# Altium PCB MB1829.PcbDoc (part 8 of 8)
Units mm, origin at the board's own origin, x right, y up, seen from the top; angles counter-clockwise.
Board outline 90 x 110 mm, 6 copper layers (Top Layer, Signal Layer 1, Signal Layer 2, Signal Layer 3, Signal Layer 4, Bottom Layer), stack 1.578 mm thick; 466 components, 354 nets, 2058 pads, 1522 vias.
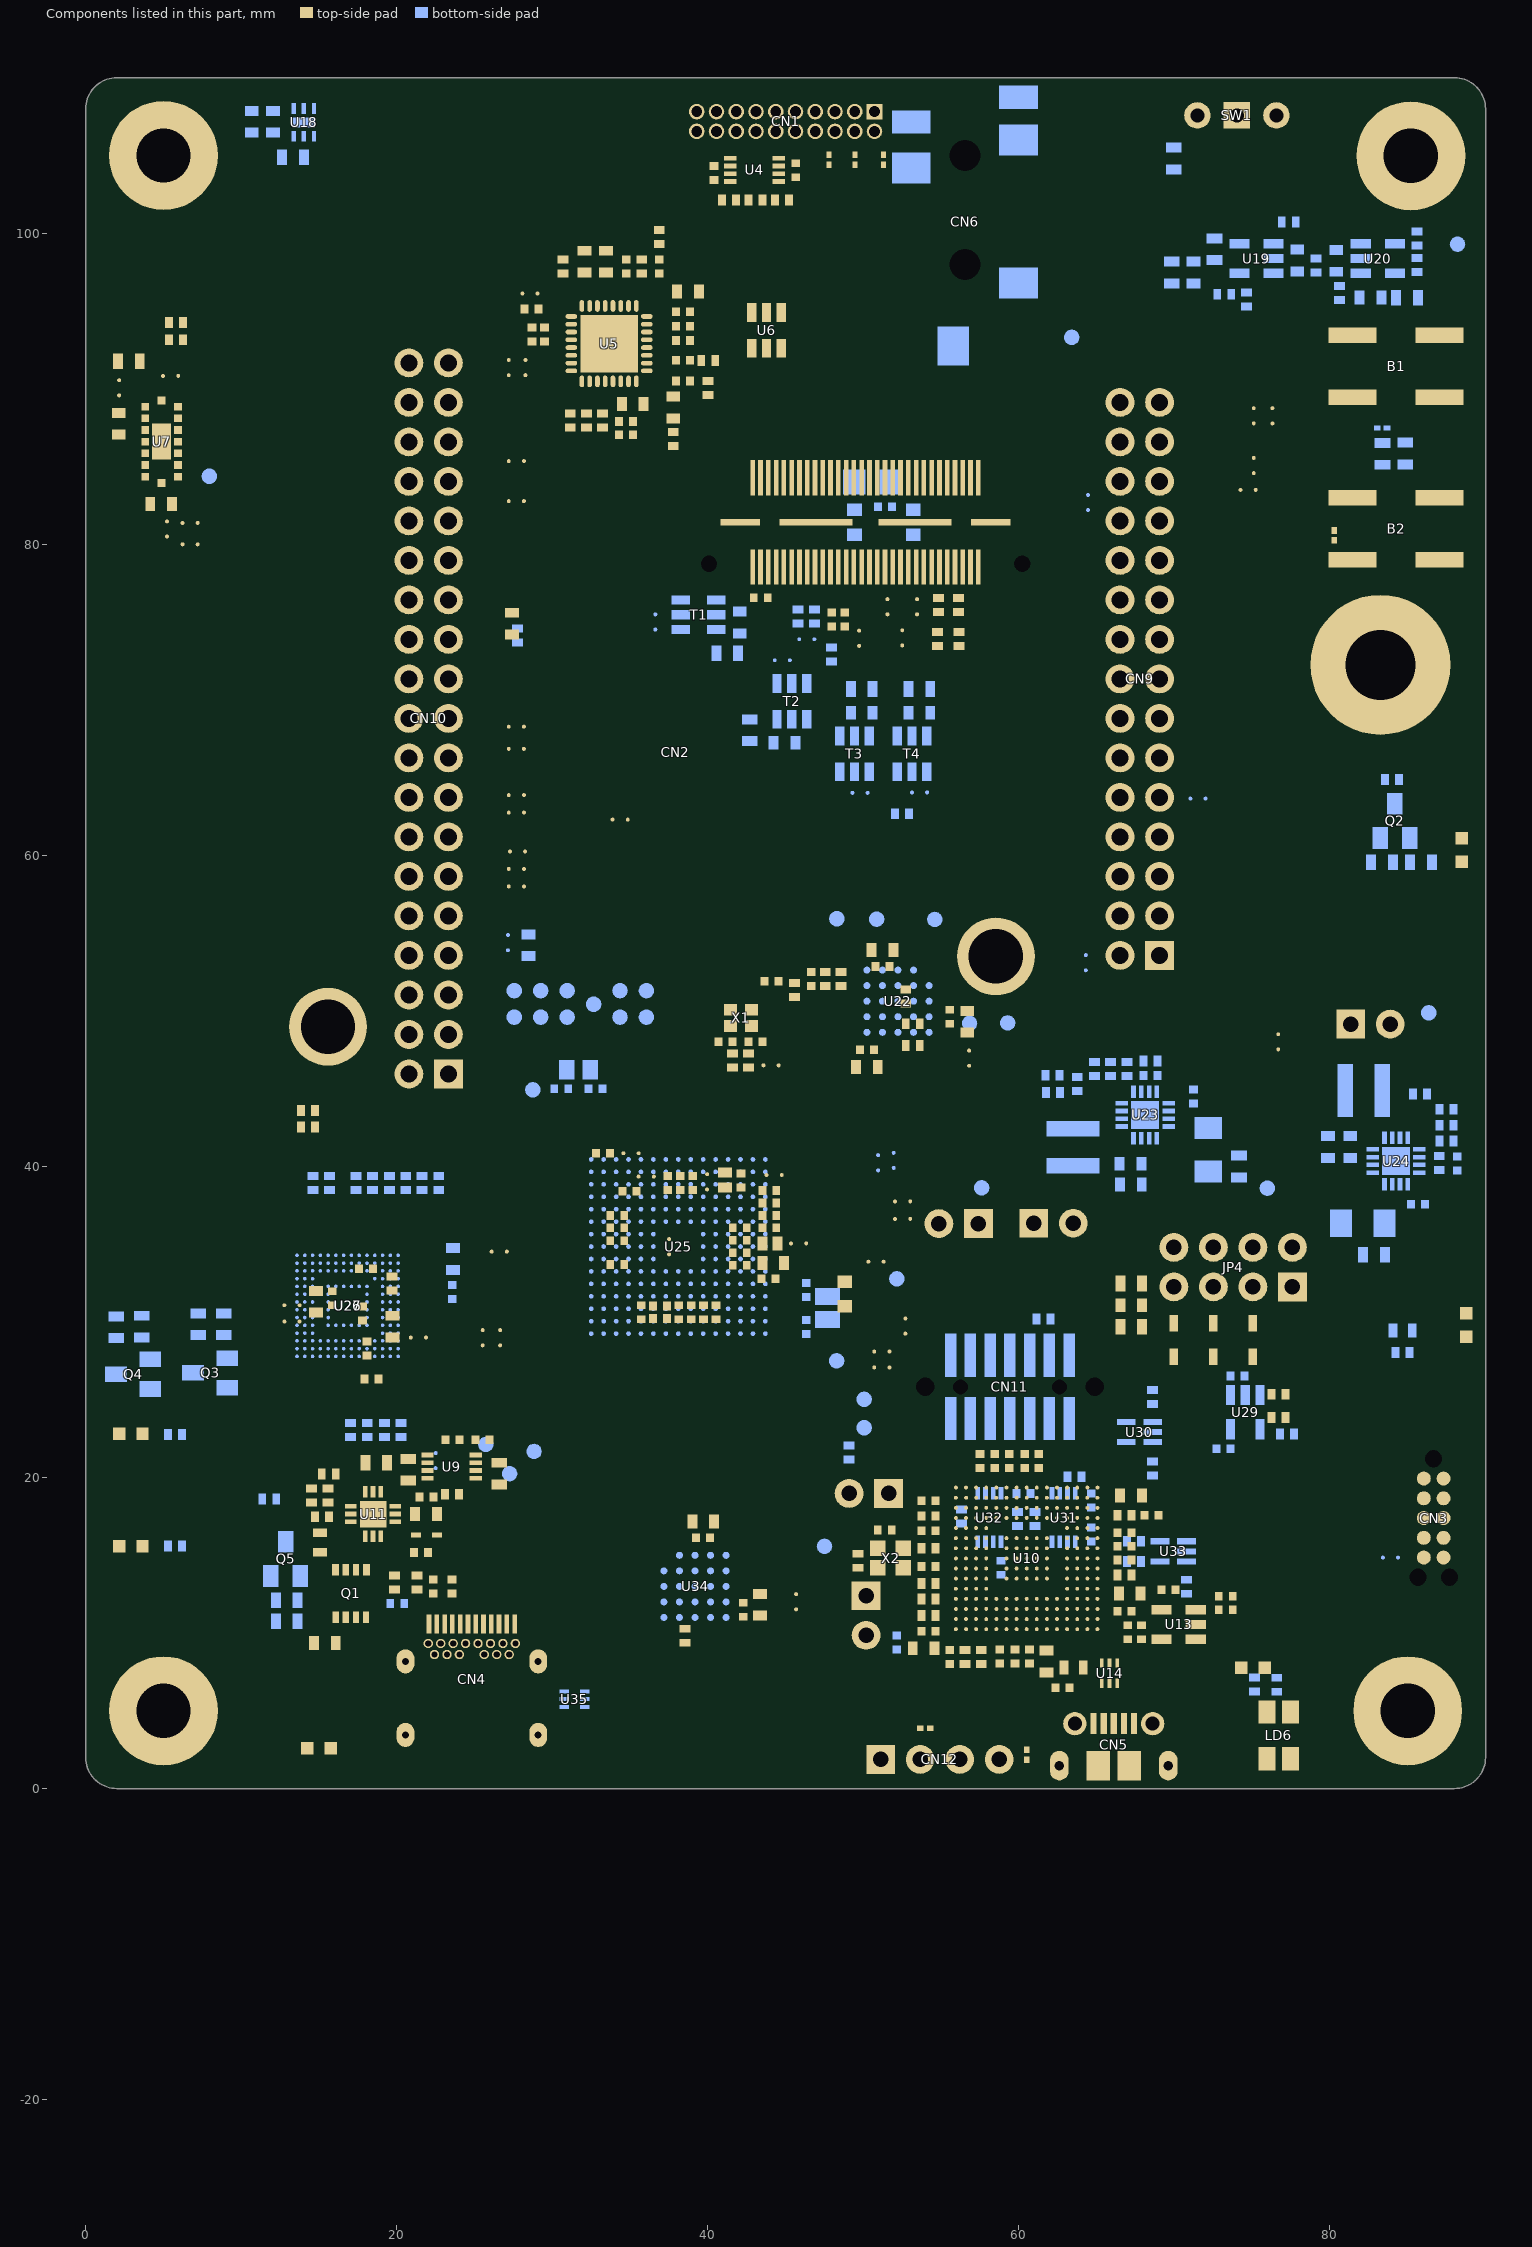
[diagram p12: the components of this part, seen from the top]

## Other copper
Top Layer:
  rectangle: 13.3,106.8 14.75,107.45
  region net GND: 88.225,34.2 88.225,36.2 87.225,36.2 87.225,34.2
  region net GND: 88.425,98.325 88.425,100.325 87.425,100.325 87.425,98.325
  region net GND: 2.425,26.8 2.425,28.8 1.425,28.8 1.425,26.8
  region net GND: 2.425,77.159 2.425,79.159 1.425,79.159 1.425,77.159
  pour cut-out: 41.45,50.675 41.725,50.95 43.4,50.95 43.65,50.7 43.65,46.018 43.2,45.568 43.2,40.654 42.726,40.18 41.749,40.18 41.245,40.684 41.245,41.66 41.7,42.115 41.7,45.25 41.475,45.475 41.009,45.475 40.725,45.759 40.725,48.199 40.575,48.349 40.575,49.925 40.725,50.075 41.15,50.075 41.45,50.375
  pour cut-out: 1.175,29.05 1.175,26.55 2.675,26.55 2.675,29.05
  pour cut-out: 1.175,79.4 1.175,76.9 2.675,76.9 2.675,79.4
  pour cut-out: 87.175,100.6 87.175,98.1 88.675,98.1 88.675,100.6
  pour cut-out: 86.975,36.45 86.975,33.95 88.475,33.95 88.475,36.45
  text "1" at 23.082,107.531 h2
  text ".Layer_Name" at 11.322,-18.839 h3
  text ".GTL" at 53.016,-18.839 h3
Signal Layer 1:
  text "2" at 24.632,107.531 h2
  text ".Layer_Name" at 11.328,-18.77 h3
  text ".G1" at 53.023,-18.77 h3
Signal Layer 2:
  pour cut-out: 25.625,11.075 25.625,8.875 25.37,8.62 24.305,8.62 23.95,8.975 23.95,11.025 24.05,11.125 25.575,11.125
  text "3" at 26.082,107.553 h2
  text ".Layer_Name" at 11.297,-18.787 h3
  text ".G2" at 52.991,-18.787 h3
Signal Layer 3:
  pour cut-out: 26.525,41.075 19.7,41.075 17.9,39.275 14.575,39.275 13.5,38.2 13.5,24.85 16.1,22.25 21.55,22.25 23.725,24.425 27.25,24.425 27.85,25.025 27.85,39.75
  pour cut-out: 36.775,13.625 37.35,13.625 39.775,11.2 39.775,9.796 39.454,9.475 38.725,9.475 38.325,9.875 38.325,10.7 36.55,12.475 36.55,13.4
  text "4" at 28.332,107.531 h2
  text ".Layer_Name" at 11.328,-18.77 h3
  text ".G3" at 53.023,-18.77 h3
Signal Layer 4:
  text "5" at 29.882,107.553 h2
  text ".Layer_Name" at 11.328,-18.77 h3
  text ".G4" at 53.023,-18.77 h3
Bottom Layer:
  pour cut-out: 66.85,42.3 66.85,40.925 66.817,40.958 61.322,40.958 61.322,41.947 61.425,42.05 61.911,41.564 65.637,41.564 66.378,42.305 66.75,42.305
  pour cut-out: 70.843,47.975 71.725,47.093 71.725,44.043 71.918,43.85 72,43.932 72,47.205 71.103,48.103
  pour cut-out: 88.3,42.302 88.649,41.953 88.825,41.953 88.825,44.146 87.296,44.146 87.124,43.975 87.124,42.726 87.557,42.293 88.3,42.293
  pour cut-out: 33.3,47.325 33.4,47.225 33.4,45.7 33.225,45.525 33.225,44.425 33.069,44.269 32.619,44.269 32.475,44.125 32.475,42.875 34.282,41.068 34.282,40.533 34.199,40.45 32.5,40.45 30.9,42.05 30.9,44 30.7,44.2 30.3,44.2 30.125,44.375 30.125,45.525 29.95,45.7 29.95,47.095 30.18,47.325
  pour cut-out: 36.875,41.55 36.875,51.994 37.927,53.046 37.927,54.476 37.309,55.095 37.309,55.875 41.486,60.051 43.209,60.051 44.199,61.041 56.022,61.041 56.235,61.254 56.235,76.399 55.783,76.851 55.783,79.993 54.35,81.426 54.35,82.058 54.35,82.75 54.362,82.738 58.031,82.738 58.043,82.75 58.043,84.398 56.231,86.21 54.81,86.21 54.412,85.813 52.887,85.813 52.887,86.726 53.652,87.49 56.761,87.49 59.173,85.078 59.173,78.102 59.625,77.65 59.625,59.85 57.471,57.696 47.371,57.696 40.225,50.55 40.225,40.375 40.122,40.272 37.339,40.272 36.75,40.861
  pour cut-out: 34.4,28.45 30.25,24.3 22.1,24.3 20.825,23.025 16.275,23.025 13.15,26.15 13.15,38.25 15.7,40.8 28.05,40.8 30.7,38.15 33.85,38.15 34.4,37.6
  pour cut-out: 31.15,23.125 31.15,10.7 32.775,9.075 45.1,9.075 46.75,10.725 46.75,23.75 41.75,28.75 41.75,30.025 39.8,31.975 36.825,31.975 35.525,30.675 35.525,27.975 34.475,26.925 34.475,26.45
  pour cut-out: 40.85,44.217 40.225,43.592 40.225,38.05 40.45,37.825 40.7,37.825 41.55,38.675 43.15,38.675 43.475,39 44.875,39 47.825,41.95 47.825,43.47 48.155,43.8 52.725,43.8 55.9,46.975 55.9,51.475 53.625,53.75 43.625,53.75 40.85,50.975
  text "6" at 31.082,107.553 h2
  text ".GBL" at 41.761,-18.675 h3
  text ".Layer_Name" at 83.075,-18.675 h3
Multi-Layer:
  pour cut-out: 6.75,101.85 17.475,101.85 17.475,109.25 6.75,109.25
  pour cut-out: 31.375,109.15 31.375,107.15 22.875,107.15 22.875,109.15

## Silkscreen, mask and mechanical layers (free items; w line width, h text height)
Top Overlay:
  drawing of 421 lines, arcs and shapes, not listed
  text "Temp" at 9.6,107.4 h1.5
  text "Pad" at 10.325,106 h1.5
  text "SW1" at 76.45,105 h1.5
  text "E" at 1.075,95.783 h10
  text "USER" at 85.425,95.525 h1.7
  text "CN10" at 19.225,93.5 h1.5
  text "PD1" at 24.8,92.4 h1.52
  text "PG8" at 16,91.2 h1.5
  text "PC4|PG14" at 71,89.6 h1.5
  text "PG7" at 16,88.7 h1.5
  text "PD0" at 24.8,88.599 h1.52
  text "PA6" at 61.7,88.599 h1.52
  text "PF5" at 16,86.3 h1.5
  text "PA5|PG13" at 71,86.3 h1.5
  text "PG0" at 24.8,86.216 h1.52
  text "CN2" at 54.8,86.099 h1.52
  text "PB1" at 61.7,86.1 h1.52
  text "RESET" at 84.625,84.9 h1.7
  text "PB10" at 61.7,83.699 h1.52
  text "PA4" at 71,83.7 h1.5
  text "PA3" at 16,83.6 h1.5
  text "PF15" at 24.8,83.499 h1.52
  text "PB11" at 61.7,81.2 h1.52
  text "PE7" at 16,81 h1.5
  text "PC5" at 71,81 h1.5
  text "PF14" at 24.8,80.6 h1.52
  text "PA0" at 71,78.5 h1.5
  text "PD15" at 16,78.4 h1.5
  text "GND" at 24.8,78.399 h1.52
  text "PB0" at 61.7,78.399 h1.52
  text "MB1829B" at 3,76.75 h2.5
  text "AGND" at 24.799,76.299 h1.52
  text "GND" at 61.7,75.999 h1.52
  text "PB2" at 71,75.9 h1.5
  text "PE11" at 16,75.8 h1.5
  text "PF12" at 16,73.3 h1.5
  text "VDDA" at 24.799,72.5 h1.52
  text "J" at 2,71.5 h12
  text "PF1" at 61.7,71 h1.52
  text "1V8" at 71,70.9 h1.5
  text "PD3" at 24.925,68.999 h1.52
  text "GND" at 71,68.5 h1.5
  text "PF0" at 61.7,68.399 h1.52
  text "PF13" at 16.2,68 h1.5
  text "GND" at 71,65.9 h1.5
  text "PA7" at 16.2,65.7 h1.5
  text "PD7" at 61.7,65.7 h1.52
  text "PB12" at 24.925,65.2 h1.52
  text "PD6" at 61.7,63.399 h1.52
  text "5V" at 71,63.3 h1.5
  text "PD10|PB13" at 29.2,63.282 h1.5
  text "PG15" at 16.2,63 h1.5
  text "/ 3V3" at 89.399,62.375 h1.7 r90
  text "VDD" at 87.8,62.05 h1.7 r90
  text "PD4|PD11" at 24.925,61.016 h1.5
  text "PB4" at 61.7,60.9 h1.52
  text "3V3" at 71,60.7 h1.5
  text "PG11" at 16.2,60.6 h1.5
  text "PB3" at 61.7,58.299 h1.52
  text "PD9" at 29.2,58.199 h1.52
  text "NRST" at 71,58.2 h1.5
  text "PG10" at 16.2,58 h1.5
  text "PB15" at 61.7,55.799 h1.52
  text "IOREF" at 71,55.7 h1.5
  text "PG9" at 16.2,55.6 h1.5
  text "PD12" at 25.125,55.508 h1.52
  text "GND" at 16.2,53.3 h1.3
  text "PE4" at 25.15,53.2 h1.52
  text "PB14" at 61.7,53.2 h1.52
  text "5V_VIN" at 71,53.2 h1.5
  text "VREFP" at 15.9,52 h1.2
  text "3V3" at 82.675,51.175 h1.7
  text "PE5" at 25.125,50.591 h1.52
  text "PE6" at 25.151,47.936 h1.52
  text "JP1" at 81.725,46.55 h1.5
  text "PE2" at 25.125,45.55 h1.52
  text "PG13" at 16,45 h1.5
  text "PG14" at 16,43.8 h1.5
  text "JP3" at 56.25,38.325 h1.5
  text "JP2" at 60.325,38.325 h1.5
  text "JP4" at 68.4,33.725 h1.5 r90
  text "VDD_MCU" at 52.8,33.575 h1.5
  text "VDD" at 62.025,33.575 h1.5
  text "5V" at 87.9,27.025 h1.7
  text "CN11" at 66.95,24.425 h1.5 r90
  text "TAG" at 86.425,24.15 h1.7
  text "USER" at 0.825,20.825 h1.7
  text "JP5" at 49,20.575 h1.5
  text "GREEN" at 0.65,19.45 h1.7
  text "USER" at 0.725,13.325 h1.7
  text "RED" at 1.425,11.8 h1.7
  text "JP6" at 48.575,10.375 h1.5 r90
  text "OVC" at 73.575,8.55 h1.5
  text "USB" at 70.2,6.475 h1.7
  text "USB" at 15.525,5.65 h1.7
  text "STLK" at 69.6,5.175 h1.7
  text "Type-C" at 14.675,4.325 h1.7
  text "3V3 / STLK" at 52.091,3.425 h1.7 r90
  text "COM" at 71.269,2.573 h1.7
  text "USBC 5V" at 9.8,0.725 h1.7
  text "CN12" at 49.35,0.425 h1.5 r90
  text ".Layer_Name" at 11.322,-18.839 h3
  text ".GTO" at 53.016,-18.839 h3
Bottom Overlay:
  lines w0.1: 20.454,0.38 20.454,1.005 ; 20.454,1.305 20.454,1.93 ; 20.454,2.255 20.454,2.4 ; 20.454,4.45 20.454,4.82 ; 20.454,5.145 20.454,5.77 ; 20.454,6.195 20.454,6.82 ; 20.454,9.275 20.454,9.52 ; 20.454,9.755 20.454,10.38 ; 20.454,10.375 20.749,10.375 ; 21.074,10.375 21.699,10.375 ; 22.089,10.375 22.714,10.375 ; 23.014,10.375 23.639,10.375 ; 23.964,10.375 24.589,10.375 ; 25.014,10.375 25.639,10.375 ; 25.939,10.375 26.564,10.375 ; 26.889,10.375 27.514,10.375 ; 27.789,10.375 28.339,10.375 ; 28.574,10.375 29.199,10.375 ; 29.194,0.38 29.194,1.005 ; 29.194,1.305 29.194,1.93 ; 29.194,2.255 29.194,2.4 ; 29.194,4.45 29.194,4.82 ; 29.194,5.145 29.194,5.77 ; 29.194,6.195 29.194,6.82 ; 29.194,9.275 29.194,9.52 ; 29.194,9.755 29.194,10.38 ; 62.1,2.525 62.1,2.94 ; 62.1,3.215 62.1,3.765 ; 62.1,4 62.1,4.625 62.6,4.625 ; 62.99,4.625 63.615,4.625 ; 63.915,4.625 64.54,4.625 ; 64.865,4.625 65.49,4.625 ; 65.32,52.039 66.195,52.039 ; 65.915,4.625 66.54,4.625 ; 66.84,4.625 67.465,4.625 ; 67.79,4.625 68.415,4.625 ; 68.69,4.625 69.24,4.625 ; 69.37,52.039 70.245,52.039 70.246,52.243 ; 69.475,4.625 70.1,4.625 70.1,4 ; 70.1,2.525 70.1,2.94 ; 70.1,3.215 70.1,3.765 ; 21.475,0.688 21.475,3.738 26.675,3.738 26.675,0.688 21.475,0.688 ; 62.19,105.7 62.19,108.775 67.415,108.775 67.415,105.7 62.19,105.7 ; 63.975,5.126 63.975,8.175 68.2,8.175 68.2,5.126 63.975,5.126
  lines w0.12: 17.775,45.875 17.775,46.2 19.225,47.65 ; 17.825,51.75 18.664,51.75 19.35,51.064 ; 24.745,50.133 25.795,49.083 25.795,48.9 ; 38.42,105.685 38.92,105.685 ; 38.42,105.894 38.42,106.894 ; 38.42,107.685 38.42,108.685 38.92,108.685 ; 39.275,80.95 39.275,81.725 ; 39.275,82.225 39.275,82.95 ; 39.275,83.5 39.275,84.275 ; 39.275,84.775 39.275,85.5 ; 39.283,79.7 39.283,80.425 ; 39.9,85.5 40.625,85.5 ; 39.92,105.685 40.92,105.685 ; 39.92,108.685 40.92,108.685 ; 41.2,85.5 41.975,85.5 ; 41.92,105.685 42.92,105.685 ; 41.92,108.685 42.92,108.685 ; 42.475,85.5 43.2,85.5 ; 43.1,77.375 43.825,77.375 ; 43.775,85.5 44.55,85.5 ; 43.92,105.685 44.92,105.685 ; 43.92,108.685 44.92,108.685 ; 44.325,77.375 45.1,77.375 ; 45.05,85.5 45.775,85.5 ; 45.92,105.685 46.92,105.685 ; 45.92,108.685 46.92,108.685 ; 46.4,85.5 47.175,85.5 ; 47.675,85.5 48.4,85.5 ; 47.92,105.685 48.92,105.685 ; 47.92,108.685 48.92,108.685 ; 49.75,77.375 50.475,77.375 ; 49.92,105.685 50.92,105.685 ; 49.92,108.685 50.92,108.685 ; 51.175,77.366 51.95,77.366 ; 51.58,105.894 51.58,106.894 ; 51.58,107.685 51.58,108.685 ; 52.45,77.366 53.175,77.366 ; 53,85.475 53.775,85.475 ; 53.783,77.382 54.558,77.382 ; 54.275,85.475 55,85.475 55.775,85.475 ; 55.058,77.382 55.783,77.382 ; 56.275,85.475 57,85.475 57.775,85.475 ; 56.375,77.375 57.15,77.375 ; 57.65,77.375 58.375,77.375 ; 58.275,85.475 59,85.475 59.775,85.475 ; 59,77.375 59.775,77.375 ; 60.275,77.375 61,77.375 61,78.025 ; 60.275,85.475 61,85.475 61,84.75 ; 61,79.425 61,80.15 ; 61,80.65 61,81.425 ; 61,81.95 61,82.675 ; 61,83.175 61,83.95 ; 75.35,26.5 76.5,26.5 76.95,26.05 ; 86.325,100.375 86.325,98.825 86.325,97.2 86.325,96.75 86.5,96.575 87.4,96.575
  text "AUDIO" at 67.15,107.35 h1.7
  text "CN1" at 38,107 h1.3
  text "JACK" at 66.85,105.975 h1.7
  text "0" at 71.975,105.8 h1.5 r90
  text "1" at 76.2,105.3 h1.5 r270
  text "CN6" at 64.9,104.35 h1.5
  text "G" at 25.175,101.65 h8
  text "BOOT0" at 73.575,101.375 h1.5 r270
  text "F" at 32.8,101.3 h10
  text "S" at 47.525,97.6 h10
  text "2V8" at 89.325,97.3 h1.7
  text "C" at 34,92.5 h10
  text "CN9" at 69,91.4 h1.5
  text "1V8" at 64.516,91.141 h1.7
  text "PG8" at 19,91 h1.5
  text "PD1" at 27.258,91 h1.5
  text "PC4|PG14" at 77.313,88.987 h1.52
  text "PA6" at 64.7,88.7 h1.5
  text "PD0" at 27.441,88.616 h1.5
  text "PG7" at 19,88.5 h1.5
  text "I" at 41,88.5 h13.5
  text "H" at 52.5,88 h16
  text "PA5|PG13" at 77.242,86.287 h1.52
  text "PB1" at 64.7,86.2 h1.5
  text "PG0" at 27.515,86.016 h1.5
  text "PF5" at 19,85.999 h1.52
  text "PB10" at 64.7,83.9 h1.5
  text "CN2" at 43.1,83.825 h1.7
  text "PF15" at 28.047,83.516 h1.5
  text "PA4" at 73.403,83.5 h1.52
  text "PA3" at 19,83.399 h1.52
  text "PF14" at 28.035,81 h1.5
  text "PC5" at 73.49,81.016 h1.52
  text "PE7" at 19,80.8 h1.52
  text "PB11" at 64.7,80.6 h1.5
  text "GND" at 27.838,78.516 h1.5
  text "PA0" at 73.404,78.516 h1.52
  text "PB0" at 64.7,78.5 h1.5
  text "PD15" at 19,78.299 h1.52
  text "AGND" at 28.301,76.014 h1.3
  text "GND" at 64.7,76 h1.5
  text "PB2" at 73.397,75.9 h1.52
  text "PE11" at 19,75.8 h1.52
  text "PF12" at 19,73.3 h1.52
  text "VDDA" at 28.723,72.3 h1.5
  text "PF1" at 64.7,70.9 h1.5
  text "1V8" at 73.215,70.816 h1.52
  text "PF0" at 64.7,68.5 h1.5
  text "PF13" at 19,68.299 h1.52
  text "PD3" at 27.444,68.316 h1.5
  text "GND" at 73.882,68.316 h1.52
  text "GND" at 73.882,65.816 h1.52
  text "PB12" at 28.106,65.8 h1.5
  text "PD7" at 64.7,65.8 h1.5
  text "PA7" at 19,65.5 h1.52
  text "PB13|PD10" at 31.815,63.482 h1.5
  text "PD6" at 64.7,63.3 h1.5
  text "5V" at 74.297,63.216 h1.52
  text "PG15" at 19,63 h1.5
  text "PD4|PD11" at 30.96,60.882 h1.5
  text "3V3" at 73.303,60.816 h1.52
  text "PB4" at 64.7,60.8 h1.5
  text "PG11" at 19,60.5 h1.5
  text "PB3" at 64.7,58.3 h1.5
  text "PD9" at 27.446,58.216 h1.5
  text "NRST" at 74.575,58.116 h1.52
  text "PG10" at 19,58 h1.5
  text "PB15" at 64.7,55.8 h1.5
  text "PD12" at 28.18,55.7 h1.5
  text "IOREF" at 74.973,55.616 h1.52
  text "PG9" at 19,55.5 h1.5
  text "PB14" at 64.7,54.2 h1.5
  text "GND" at 19,53.2 h1.5
  text "5V_VIN" at 75.524,53.171 h1.52
  text "PE4" at 27.366,52.3 h1.5
  text "VREFP" at 19,52 h1.5
  text "IDD / 3V3" at 82,51.3 h1.7 r270
  text "2" at 66.025,51.125 h1.5 r270
  text "PJ3" at 37.25,50.55 h1.5 r270
  text "PJ6" at 38.7,50.55 h1.5 r270
  text "PJ5" at 40.3,50.55 h1.5 r270
  text "PJ1" at 42.925,50.55 h1.5 r270
  text "PJ9" at 44.25,50.55 h1.5 r270
  text "PJ8" at 41.625,49.325 h1.5 r270
  text "3V3" at 87.65,48.55 h1.7 r270
  text "PJ4" at 38.7,48.025 h1.5 r270
  text "PJ7" at 40.3,48.025 h1.5 r270
  text "PJ2" at 37.275,47.975 h1.5 r270
  text "PE5" at 27.377,47.716 h1.5
  text "PJ11" at 44.275,47.45 h1.5 r270
  text "PJ10" at 42.925,47.275 h1.5 r270
  text "OP1" at 58.184,47.234 h1.5
  text "OP2" at 61.186,47.236 h1.5
  text "PE6" at 27.369,46.516 h1.5
  text "PE2" at 27.36,45.3 h1.5
  text "PG13" at 19,44.7 h1.5
  text "PG14" at 19,43.5 h1.5
  text "2" at 20.3,43.5 h1.5 r270
  text "VDD" at 59.275,40.8 h1.7
  text "PG12" at 28.225,40.725 h1.5 r270
  text "MCU" at 59.05,39.575 h1.7
  text "5V" at 78.6,38.1 h1.7
  text "PE15" at 53.575,33.725 h1.5
  text "IDD" at 62.975,33.525 h1.7
  text "IDD / MCU" at 57.9,32.025 h1.7
  text "E5V" at 74.5,27.9 h1.7 r270
  text "STLK" at 77.075,27.15 h1.7 r270
  text "PD13" at 47.275,27 h1.5
  text "USBC" at 71.975,26.6 h1.7 r270
  text "CHGR" at 69.475,26.3 h1.7 r270
  text "PG2" at 48.775,24.65 h1.5
  text "DEBUG" at 51.25,23.275 h1.7 r270
  text "PG4" at 48.825,22.875 h1.5
  text "PG6" at 25.275,18.525 h1.5 r270
  text "PG5" at 28.35,18.1 h1.5 r270
  text "PG3" at 26.75,16.8 h1.5 r270
  text "TNRST" at 52.95,16.15 h1.7
  text "PD14" at 45.55,13.963 h1.5 r270
  text "CN3" at 88.075,11.25 h1.5
  text "STLK_NRST" at 47.4,7.625 h1.4 r270
  text "USB" at 67.5,6.85 h1.7
  text "STLK" at 67.941,5.441 h1.7
  text "SWCLK" at 53.225,4.05 h1.7 r270
  text "GND" at 55.8,3.925 h1.7 r270
  text "SWIO" at 58.125,3.875 h1.7 r270
  text "3V3 / STLK" at 51.9,3.65 h1.7
  text "USB" at 25.6,2.45 h1.7
  text "CN5" at 67.1,2.275 h1.5
  text "K" at 42.04,1.97 h12
  text "Type-C" at 26.525,1.275 h1.7
  text "CN4" at 32.05,0.8 h1.5
  text ".GBO" at 41.788,-18.819 h3
  text ".Layer_Name" at 83.102,-18.819 h3
Top Paste:
  text ".Layer_Name" at 11.322,-18.839 h3
  text ".GTP" at 53.016,-18.839 h3
Bottom Paste:
  text ".GBP" at 41.761,-18.675 h3
  text ".Layer_Name" at 83.075,-18.675 h3
Top Solder:
  region: 31.375,109.15 22.875,109.15 22.875,107.15 31.375,107.15
  text ".Layer_Name" at 11.322,-18.839 h3
  text ".GTS" at 53.016,-18.839 h3
Bottom Solder:
  region: 31.375,109.15 22.875,109.15 22.875,107.15 31.375,107.15
  text ".GBS" at 41.761,-18.675 h3
  text ".Layer_Name" at 83.075,-18.675 h3
M1-Board Shape:
  lines w0.1: 0,2 ccw(c2,2) 2,0 88,0 ccw(c88,2) 90,2 90,108 ccw(c88,108) 88,110 2,110 ccw(c2,108) 0,108 0,2
  lines w0.12: 15.625,102.35 15.65,102.35 cw(c15.65,102.1) 15.9,102.1 cw(c15.65,102.1) 15.65,101.85 9.15,101.85 cw(c9.15,102.1) 8.9,102.1 ; 15.637,102.35 9.15,102.35 ccw(c9.15,102.1) 8.9,102.1 ; 17.475,102.975 cw(c17.25,102.975) 17.25,102.75 cw(c17.25,103.025) 16.975,103.025 16.975,107.575 cw(c17.225,107.575) 17.225,107.825 cw(c17.225,107.575) 17.475,107.575 17.475,103.025 ; 8.9,102.1 8.9,102.1
M2-Board Dimensions:
  text ".Layer_Name" at 11.322,-18.839 h3
  text ".GM2" at 53.016,-18.839 h3
M3-Top Dimensions:
  circle w0.1: c83.241,72.252 r2.25
  circle w0.1: c85,5 r1.75
  circle w0.1: c5,5 r1.75
  circle w0.1: c5,105 r1.75
  circle w0.1: c85.2,104.975 r1.75
M7-Top Info:
  lines w0.12: 16.64,10.05 14.904,10.05 9.998,5.144 cw(c5,5) 4.944,10 10.123,15.178 10.123,16.565 cw(c45,45) 79.877,16.565 79.877,15.178 85.056,10 cw(c85,5) 80.002,5.144 75.096,10.05 73.36,10.05 ; 16.646,10.057 ccw(c45,45) 27.6,3.5 62.4,3.5 ; 62.41,3.504 ccw(c45,45) 73.354,10.057
  text "MB1835B" at 33.697,45.038 h7
M8-Bottom Info:
  lines w0.1: 18.546,63.232 cw(c34.306,68.479) 26.306,83.035 26.306,87.479 62.306,87.479 62.306,49.479 37.056,49.479 37.056,51.979 ; 21.563,57.825 ccw(c34.306,68.479) 26.306,53.922 26.306,49.479 31.556,49.479 31.556,51.979 ; 24.579,85.479 39.579,85.479 ; 24.582,85.473 ccw(c32.96,66.217) 15.079,77.229 15.079,66.479 12.079,66.479 12.079,45.479 61.579,45.479 61.579,88.479 39.579,88.479 ; 153.106,158.027 156.106,158.027
  lines w0.12: 18.546,63.232 19.99,64.159 23.007,58.751 21.563,57.825 ; 31.556,51.979 37.056,51.979 ; 35.667,62.082 35.667,89.052 88.497,89.052 88.497,62.082 35.667,62.082
  text "MB1232A" at 47.35,74.487 h7
  text "MB1314C" at 30.426,66.851 h7
  text "MB1650C" at 24.679,63.329 h7
M14-Top Assembly:
  text ".Layer_Name" at 11.322,-18.839 h3
  text ".GM14" at 53.016,-18.839 h3
M15-Bottom Assembly:
  text ".GM15" at 41.761,-18.675 h3
  text ".Layer_Name" at 83.075,-18.675 h3
Drill Drawing:
  drawing of 558 lines, arcs and shapes, not listed
  text "THE COMPONENTS WITH PLATED THROUGH HOLE (PTH) MAY BE WELDED (CABLED) IN \"PIN-IN-PASTE\" MODE (IF NECESSARY)" at 3.298,155.754 h1.52
  text "PCB SPECIFICATIONS :" at 3.873,151.004 h3
  text "PCB : TYPE 3" at 152.285,150.771 h3
  text "A.   MATERIAL :" at 3.873,147.004 h3
  text "FR-4" at 42.373,147.004 h3
  text "TG-170" at 58.873,147.004 h3
  text "X  TG-150" at 77.123,147.004 h3
  text "TG-140" at 93.123,147.004 h3
  text "ASPECT-RATIO, AXE Z :" at 152.285,145.271 h3
  text "B.   MATERIAL FAMILY :" at 3.873,144.004 h3
  text "N/A" at 42.373,144.004 h3
  text "C.   SOLDERMASK COLOR :" at 3.873,141.004 h3
  text "GREEN" at 42.373,141.004 h3
  text "WHITE" at 58.873,141.004 h3
  text "RED" at 77.123,141.004 h3
  text "X  Blue ink PANTONE 2955" at 93.123,141.004 h3
  text "6:1 to 8:1 / LEVEL \"B\"" at 152.573,139.804 h3
  text "D.   SILKSCREEN COLOR :" at 3.873,138.004 h3
  text "X  WHITE" at 42.373,138.004 h3
  text "YELLOW" at 58.873,138.004 h3
  text "BLACK" at 77.123,138.004 h3
  text "Blue ink PANTONE 2955" at 93.123,138.004 h3
  text "E.   SURFACE FINISH :" at 3.873,135.004 h3
  text "X  ENIG" at 42.373,135.004 h3
  text "IMMERSION SILVER" at 58.873,135.004 h3
  text "IMMERSION TIN" at 93.123,135.004 h3
  text "MINIMUM PARAMETERS" at 152.331,132.923 h3
  text "HASL" at 42.373,132.004 h3
  text "HASL (PB-FREE)" at 58.873,132.004 h3
  text "GOLDEN FINGER" at 93.123,132.004 h3
  text "F.   IMPEDANCE CONTROL :" at 3.873,129.004 h3
  text "NO" at 42.373,129.004 h3
  text "X  YES  (SEE IMPEDANCE TABLE FOR DETAIL INFORMATION)" at 58.873,129.004 h3
  text "DEFAULT" at 152.331,127.423 h3
  text "G.   THROUGH VIA :" at 3.873,126.004 h3
  text "PLUG THE VIAS WHICH ARE COVERED WITH SOLDERMASK ONE OR TWO SIDE." at 42.373,126.004 h3
  text "PLUG MATERIAL :" at 42.373,123.004 h3
  text "X  SOLDERMASK" at 67.873,123.004 h3
  text "NON-CONDUCTIVE EPOXY." at 93.123,123.004 h3
  text "TRACKS : 0.08mm           / GAPS : 0.085mm" at 152.273,121.904 h3
  text "H.   STACK-UP :" at 3.873,120.004 h3
  text "SEE LAYER STACK-UP SEQUENCE FOR OVERALL THICKNESS." at 42.373,120.004 h3
  text "Symbol" at 133.228,108.097 h2.4
  text "Count" at 142.626,108.097 h2.4
  text "Hole Size" at 153.239,108.097 h2.4
  text "Plated" at 172.529,108.097 h2.4
  text "Hole Type" at 180.778,108.097 h2.4
  text "Drill Layer Pair" at 192.785,108.097 h2.4
  text "Via/Pad" at 219.548,108.097 h2.4
  text "Pad Shape" at 229.387,108.097 h2.4
  text "14" at 142.626,103.955 h2
  text "0,400mm (15,75mil)" at 153.239,103.955 h2
  text "PTH" at 172.529,103.955 h2
  text "Round" at 180.778,103.955 h2
  text "Top Layer - Bottom Layer" at 192.785,103.955 h2
  text "Pad" at 219.548,103.955 h2
  text "Rounded" at 229.387,103.955 h2
  text "4" at 142.626,99.813 h2
  text "0,450mm (17,72mil)" at 153.239,99.813 h2
  text "PTH" at 172.529,99.813 h2
  text "Slot" at 180.778,99.813 h2
  text "Top Layer - Bottom Layer" at 192.785,99.813 h2
  text "Pad" at 219.548,99.813 h2
  text "Rounded" at 229.387,99.813 h2
  text "2" at 142.626,95.671 h2
  text "0,600mm (23,62mil)" at 153.239,95.671 h2
  text "PTH" at 172.529,95.671 h2
  text "Slot" at 180.778,95.671 h2
  text "Top Layer - Bottom Layer" at 192.785,95.671 h2
  text "Pad" at 219.548,95.671 h2
  text "Rounded" at 229.387,95.671 h2
  text "20" at 142.626,91.529 h2
  text "0,700mm (27,56mil)" at 153.239,91.529 h2
  text "PTH" at 172.529,91.529 h2
  text "Round" at 180.778,91.529 h2
  text "Top Layer - Bottom Layer" at 192.785,91.529 h2
  text "Pad" at 219.548,91.529 h2
  text "Rounded" at 229.387,91.529 h2
  text "H" at 132.44,91.275 h1.84
  text "5" at 142.626,87.387 h2
  text "0,900mm (35,43mil)" at 153.239,87.387 h2
  text "PTH" at 172.529,87.387 h2
  text "Round" at 180.778,87.387 h2
  text "Top Layer - Bottom Layer" at 192.785,87.387 h2
  text "Pad" at 219.548,87.387 h2
  text "(Mixed)" at 229.387,87.387 h2
  text "2" at 142.626,83.245 h2
  text "0,970mm (38,19mil)" at 153.239,83.245 h2
  text "NPTH" at 172.529,83.245 h2
  text "Round" at 180.778,83.245 h2
  text "Top Layer - Bottom Layer" at 192.785,83.245 h2
  text "Pad" at 219.548,83.245 h2
  text "Rounded" at 229.387,83.245 h2
  text "22" at 142.626,79.103 h2
  text "1,000mm (39,37mil)" at 153.239,79.103 h2
  text "PTH" at 172.529,79.103 h2
  text "Round" at 180.778,79.103 h2
  text "Top Layer - Bottom Layer" at 192.785,79.103 h2
  text "Pad" at 219.548,79.103 h2
  text "Rounded" at 229.387,79.103 h2
  text "2" at 142.626,74.962 h2
  text "1,050mm (41,34mil)" at 153.239,74.962 h2
  text "NPTH" at 172.529,74.962 h2
  text "Round" at 180.778,74.962 h2
  text "Top Layer - Bottom Layer" at 192.785,74.962 h2
  text "Pad" at 219.548,74.962 h2
  text "Rounded" at 229.387,74.962 h2
  text "3" at 142.626,70.82 h2
  text "1,100mm (43,31mil)" at 153.239,70.82 h2
  text "NPTH" at 172.529,70.82 h2
  text "Round" at 180.778,70.82 h2
  text "Top Layer - Bottom Layer" at 192.785,70.82 h2
  text "Pad" at 219.548,70.82 h2
  text "Rounded" at 229.387,70.82 h2
  text "68" at 142.626,66.678 h2
  text "1,100mm (43,31mil)" at 153.239,66.678 h2
  text "PTH" at 172.529,66.678 h2
  text "Round" at 180.778,66.678 h2
  text "Top Layer - Bottom Layer" at 192.785,66.678 h2
  text "Pad" at 219.548,66.678 h2
  text "Rounded" at 229.387,66.678 h2
  text "2" at 142.626,62.536 h2
  text "1,190mm (46,85mil)" at 153.239,62.536 h2
  text "NPTH" at 172.529,62.536 h2
  text "Round" at 180.778,62.536 h2
  text "Top Layer - Bottom Layer" at 192.785,62.536 h2
  text "Pad" at 219.548,62.536 h2
  text "Rounded" at 229.387,62.536 h2
  text "2" at 142.626,58.394 h2
  text "2,000mm (78,74mil)" at 153.239,58.394 h2
  text "NPTH" at 172.529,58.394 h2
  text "Round" at 180.778,58.394 h2
  text "Top Layer - Bottom Layer" at 192.785,58.394 h2
  text "Pad" at 219.548,58.394 h2
  text "Rounded" at 229.387,58.394 h2
  text "2" at 142.626,54.252 h2
  text "3,200mm (125,98mil)" at 153.239,54.252 h2
  text "PTH" at 172.529,54.252 h2
  text "Round" at 180.778,54.252 h2
  text "Top Layer - Bottom Layer" at 192.785,54.252 h2
  text "Pad" at 219.548,54.252 h2
  text "Rounded" at 229.387,54.252 h2
  text "6" at 142.626,50.11 h2
  text "3,500mm (137,79mil)" at 153.239,50.11 h2
  text "PTH" at 172.529,50.11 h2
  text "Round" at 180.778,50.11 h2
  text "Top Layer - Bottom Layer" at 192.785,50.11 h2
  text "Pad" at 219.548,50.11 h2
  text "Rounded" at 229.387,50.11 h2
  text "1" at 142.626,45.968 h2
  text "4,500mm (177,17mil)" at 153.239,45.968 h2
  text "PTH" at 172.529,45.968 h2
  text "Round" at 180.778,45.968 h2
  text "Top Layer - Bottom Layer" at 192.785,45.968 h2
  text "Pad" at 219.548,45.968 h2
  text "Rounded" at 229.387,45.968 h2
  text "G" at 132.44,45.715 h1.84
  text "119" at 142.626,41.827 h2
  text "0,100mm (3,94mil)" at 153.239,41.827 h2
  text "PTH" at 172.529,41.827 h2
  text "Round" at 180.778,41.827 h2
  text "Signal Layer 3 - Signal Layer 4" at 192.785,41.827 h2
  text "Via" at 219.548,41.827 h2
  text "Rounded" at 229.387,41.827 h2
  text "E" at 132.44,41.573 h1.84
  text "274" at 142.626,37.685 h2
  text "0,100mm (3,94mil)" at 153.239,37.685 h2
  text "PTH" at 172.529,37.685 h2
  text "Round" at 180.778,37.685 h2
  text "Signal Layer 4 - Bottom Layer" at 192.785,37.685 h2
  text "Via" at 219.548,37.685 h2
  text "Rounded" at 229.387,37.685 h2
  text "20" at 142.626,33.543 h2
  text "0,100mm (3,94mil)" at 153.239,33.543 h2
  text "PTH" at 172.529,33.543 h2
  text "Round" at 180.778,33.543 h2
  text "Signal Layer 1 - Signal Layer 2" at 192.785,33.543 h2
  text "Via" at 219.548,33.543 h2
  text "Rounded" at 229.387,33.543 h2
  text "A" at 132.44,33.289 h1.84
  text "47" at 142.626,29.401 h2
  text "0,100mm (3,94mil)" at 153.239,29.401 h2
  text "PTH" at 172.529,29.401 h2
  text "Round" at 180.778,29.401 h2
  text "Top Layer - Signal Layer 1" at 192.785,29.401 h2
  text "Via" at 219.548,29.401 h2
  text "Rounded" at 229.387,29.401 h2
  text "1062" at 142.626,25.259 h2
  text "0,200mm (7,87mil)" at 153.239,25.259 h2
  text "PTH" at 172.529,25.259 h2
  text "Round" at 180.778,25.259 h2
  text "Top Layer - Bottom Layer" at 192.785,25.259 h2
  text "Via" at 219.548,25.259 h2
  text "Rounded" at 229.387,25.259 h2
  text "B" at 132.44,25.005 h1.84
  text "1677 Total" at 142.626,21.117 h2
  text "Slot definitions :" at 133.228,18.218 h2
  text "Routed Path Length" at 146.852,18.218 h2
  text "= Calculated from tool start centre position to tool end centre position." at 163.733,18.218 h2
  text "Hole Length" at 146.852,16.561 h2
  text "= Routed Path Length + Tool Size = Slot length as defined in the PCB layout" at 157.468,16.561 h2
  text "Layer" at 133.789,13.566 h2
  text "Name" at 142.154,13.566 h2
  text "Material" at 158.327,13.566 h2
  text "Thickness" at 173.685,13.566 h2
  text "Constant" at 185.628,13.566 h2
  text "Board Layer Stack" at 196.682,13.566 h2
  text "Top Overlay" at 142.154,9.566 h2
  text "Top Solder" at 142.154,5.566 h2
  text "Solder Resist" at 158.327,5.566 h2
  text "0,015mm" at 173.685,5.566 h2
  text "3,5" at 185.628,5.566 h2
  text "1" at 133.789,1.566 h2
  text "Top Layer" at 142.154,1.566 h2
  text "Copper" at 158.327,1.566 h2
  text "0,042mm" at 173.685,1.566 h2
  text "Dielectric 1" at 142.154,-2.434 h2
  text "1080HR RC68" at 158.327,-2.434 h2
  text "0,076mm" at 173.685,-2.434 h2
  text "4,2" at 185.628,-2.434 h2
  text "2" at 133.787,-6.434 h2
  text "Signal Layer 1" at 142.154,-6.434 h2
  text "Copper" at 158.327,-6.434 h2
  text "0,035mm" at 173.685,-6.434 h2
  text "Dielectric3" at 142.154,-10.434 h2
  text "1080HR RC68" at 158.327,-10.434 h2
  text "0,076mm" at 173.685,-10.434 h2
  text "4,2" at 185.628,-10.434 h2
  text "3" at 133.789,-14.434 h2
  text "Signal Layer 2" at 142.154,-14.434 h2
  text "Copper" at 158.327,-14.434 h2
  text "0,035mm" at 173.685,-14.434 h2
  text "Dielectric4" at 142.154,-18.434 h2
  text "FR-4" at 158.327,-18.434 h2
  text "1,050mm" at 173.685,-18.434 h2
  text "4,2" at 185.628,-18.434 h2
  text ".Layer_Name" at 11.322,-18.839 h3
  text ".DRL" at 53.016,-18.839 h3
  text "4" at 133.789,-22.434 h2
  text "Signal Layer 3" at 142.154,-22.434 h2
  text "Copper" at 158.327,-22.434 h2
  text "0,035mm" at 173.685,-22.434 h2
  text "Dielectric5" at 142.154,-26.434 h2
  text "1080HR RC68" at 158.327,-26.434 h2
  text "0,076mm" at 173.685,-26.434 h2
  text "4,2" at 185.628,-26.434 h2
  text "5" at 133.789,-30.434 h2
  text "Signal Layer 4" at 142.154,-30.434 h2
  text "Copper" at 158.327,-30.434 h2
  text "0,035mm" at 173.685,-30.434 h2
  text "Dielectric2" at 142.154,-34.434 h2
  text "1080HR RC68" at 158.327,-34.434 h2
  text "0,076mm" at 173.685,-34.434 h2
  text "4,2" at 185.628,-34.434 h2
  text "6" at 133.789,-38.434 h2
  text "Bottom Layer" at 142.154,-38.434 h2
  text "Copper" at 158.327,-38.434 h2
  text "0,042mm" at 173.685,-38.434 h2
  text "Bottom Solder" at 142.154,-42.434 h2
  text "Solder Resist" at 158.327,-42.434 h2
  text "0,015mm" at 173.685,-42.434 h2
  text "3,5" at 185.628,-42.434 h2
  text "Bottom Overlay" at 142.154,-46.434 h2
M20-Top Title Box:
  circle w0.254: c89.326,-25.56 r1.3
  region: 74.848,-26.653 64.092,-26.653 65.085,-24.16 72.943,-24.16 73.391,-23.401 75.6,-25.949
  region: 88.851,-18.324 73.324,-18.324 72.629,-20.099 71.419,-21.324 70.022,-19.464 70.022,-17.813 71.165,-16.416 72.601,-16.038 88.851,-16.038
  lines w0.254: 65.085,-24.16 73.877,-24.16 70.811,-20.622 cw(c72.615,-18.679) 72.855,-16.038 89.619,-16.038 88.857,-18.324 ; 68.399,-15.79 cw(c70.825,-16.761) 71.062,-14.159 ; 68.438,-15.758 64.092,-26.653 83.414,-26.653 ccw(c83.663,-23.919) 86.212,-24.938 ; 70.178,-19.693 75.6,-25.949 ; 70.432,-19.693 75.737,-25.814 ; 70.432,-19.439 75.737,-25.56 ; 70.53,-18.324 83.523,-18.324 ; 70.559,-19.312 75.864,-25.433 ; 70.686,-19.185 75.991,-25.306 ; 70.813,-19.058 76.118,-25.179 ; 70.94,-18.931 76.245,-25.052 ; 70.994,-16.978 76.299,-23.099 ; 71.063,-14.159 90.512,-14.159 86.213,-24.936 ; 71.067,-18.804 76.317,-24.862 ; 71.067,-18.55 76.372,-24.671 ; 71.067,-18.296 76.372,-24.417 ; 71.067,-17.407 76.372,-23.528 ; 71.194,-18.169 76.499,-24.29 ; 71.194,-17.788 76.499,-23.909 ; 72.565,-24.174 ccw(c72.67,-23.638) 72.968,-23.181 ; 73.652,-18.31 ccw(c73.626,-18.878) 73.296,-19.34 75.661,-22.068 cw(c73.857,-24.012) 74.589,-26.561 ; 79.933,-26.449 82.823,-18.07 ; 80.156,-26.399 83.025,-18.078 ; 80.283,-26.399 83.152,-18.078 ; 80.537,-26.399 83.406,-18.078 ; 80.791,-26.399 83.66,-18.078 ; 81.045,-26.399 83.914,-18.078 ; 81.299,-26.399 84.168,-18.078 ; 81.553,-26.399 84.422,-18.078 ; 81.807,-26.399 84.676,-18.078 ; 82.061,-26.399 84.93,-18.078 ; 82.269,-26.449 85.159,-18.07 ; 85.159,-18.324 88.851,-18.324 ; 88.183,-18.321 88.945,-16.035 ; 88.349,-18.324 89.111,-16.038 ; 88.603,-18.324 89.365,-16.038
  lines w0.3: 2.321,-25.539 62.321,-25.539 ; 2.321,-20.539 62.321,-20.539 ; 2.321,-15.539 62.321,-15.539 ; 42.321,-30.539 42.321,-15.539 ; 62.321,-30.539 62.321,-10.539 ; 79.933,-26.449 82.269,-26.449 ; 2.321,-30.539 92.321,-30.539 92.321,-10.539 2.321,-10.539 2.322,-30.539
  text "Project: '.Board_Name'" at 3.322,-13.755 h3
  text "Layer:" at 3.322,-18.839 h3
  text "Gerber:" at 43.31,-18.839 h3
  text "Variant: '.VariantName'" at 3.322,-23.839 h3
  text "Ref: MB1829" at 43.437,-23.839 h3
  text "R" at 88.818,-26.322 h1.52
  text "Date: '.Board_Document_Date'" at 3.322,-28.839 h3
  text "Rev: '.Board_PCB_Revision'" at 43.38,-28.839 h3
M21-Bottom Title Box:
  circle w0.254: c5.479,-25.508 r1.3
  region: 5.954,-18.272 21.481,-18.272 22.176,-20.047 23.386,-21.272 24.783,-19.412 24.783,-17.761 23.64,-16.364 22.204,-15.986 5.954,-15.986
  region: 19.957,-26.601 30.713,-26.601 29.72,-24.108 21.862,-24.108 21.414,-23.349 19.205,-25.897
  lines w0.254: 5.44,-15.986 6.202,-18.272 ; 5.694,-15.986 6.456,-18.272 ; 5.86,-15.983 6.622,-18.269 ; 5.948,-18.272 5.186,-15.986 21.95,-15.986 cw(c22.19,-18.627) 23.994,-20.57 20.928,-24.108 29.72,-24.108 ; 5.954,-18.272 9.646,-18.272 ; 8.592,-24.884 4.293,-14.107 23.742,-14.107 ; 8.593,-24.886 ccw(c11.142,-23.867) 11.391,-26.601 30.713,-26.601 26.367,-15.706 ; 9.646,-18.018 12.536,-26.397 ; 9.875,-18.026 12.744,-26.347 ; 10.129,-18.026 12.998,-26.347 ; 10.383,-18.026 13.252,-26.347 ; 10.637,-18.026 13.506,-26.347 ; 10.891,-18.026 13.76,-26.347 ; 11.145,-18.026 14.014,-26.347 ; 11.282,-18.272 24.275,-18.272 ; 11.399,-18.026 14.268,-26.347 ; 11.653,-18.026 14.522,-26.347 ; 11.78,-18.026 14.649,-26.347 ; 11.982,-18.018 14.872,-26.397 ; 18.306,-24.238 23.611,-18.117 ; 18.306,-23.857 23.611,-17.736 ; 18.433,-24.619 23.738,-18.498 ; 18.433,-24.365 23.738,-18.244 ; 18.433,-23.476 23.738,-17.355 ; 18.488,-24.81 23.738,-18.752 ; 18.506,-23.047 23.81,-16.926 ; 18.56,-25 23.865,-18.879 ; 18.687,-25.127 23.992,-19.006 ; 18.814,-25.254 24.119,-19.133 ; 18.941,-25.381 24.246,-19.26 ; 19.068,-25.762 24.373,-19.641 ; 19.068,-25.508 24.373,-19.387 ; 19.205,-25.897 24.627,-19.641 ; 20.216,-26.509 cw(c20.948,-23.96) 19.144,-22.016 21.509,-19.288 ccw(c21.179,-18.826) 21.153,-18.258 ; 21.837,-23.129 ccw(c22.135,-23.586) 22.24,-24.122 ; 23.743,-14.107 cw(c23.98,-16.709) 26.406,-15.738
  lines w0.3: 12.536,-26.397 14.872,-26.397 ; 32.296,-30.487 32.296,-10.487 ; 32.296,-25.487 92.296,-25.487 ; 32.296,-20.487 92.296,-20.487 ; 32.296,-15.487 92.296,-15.487 ; 52.296,-30.487 52.296,-15.487 ; 2.296,-30.487 2.296,-10.487 92.296,-10.487 92.296,-30.487 2.296,-30.487
  text "Project: '.Board_Name'" at 91.102,-13.703 h3
  text "Gerber:" at 51.114,-18.787 h3
  text "Layer:" at 91.102,-18.787 h3
  text "Ref: MB1829" at 51.114,-23.787 h3
  text "Variant: '.VariantName'" at 91.102,-23.787 h3
  text "R" at 5.987,-26.27 h1.52
  text "Rev: '.Board_PCB_Revision'" at 51.171,-28.787 h3
  text "Date: '.Board_Document_Date'" at 91.102,-28.787 h3

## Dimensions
60.043,52.657 to 61.8,51.375 on M3-Top Dimensions
59.756,51.31 to 62.35,49.6 on M3-Top Dimensions
23.32,68.804 to 23.32,71.344 on M4-Bottom Dimensions
69.04,71.344 to 69.04,73.884 on M4-Bottom Dimensions
66.5,89.124 to 69.04,89.124 on M4-Bottom Dimensions
19.575,93.189 to 24.525,93.189 on M4-Bottom Dimensions
39.285,107.82 to 39.285,106.55 on M4-Bottom Dimensions
58.519,53.51 to 90,2 on M3-Top Dimensions
83.241,72.252 to 81.025,69.725 on M3-Top Dimensions
7.45,2.432 to 10.425,1.35 on M3-Top Dimensions
14.394,46.745 to 11.363,44.66 on M3-Top Dimensions
50.715,107.82 to 49.445,107.82 on M4-Bottom Dimensions
50.715,107.82 to 90,108 on M3-Top Dimensions
50.715,107.82 to 88,110 on M3-Top Dimensions
38.42,108.685 to 38.42,105.685 on M3-Top Dimensions
38.42,108.685 to 51.58,108.685 on M3-Top Dimensions
40.074,78.74 to 60.204,78.74 on M3-Top Dimensions
65.295,52.039 to 70.245,52.039 on M4-Bottom Dimensions
20.78,45.944 to 23.32,45.944 on M4-Bottom Dimensions
19.575,44.419 to 70.245,52.039 on M4-Bottom Dimensions
19.575,93.189 to 19.575,44.419 on M4-Bottom Dimensions
70.245,90.649 to 70.245,52.039 on M4-Bottom Dimensions
69.04,89.124 to 69.04,53.564 on M4-Bottom Dimensions
20.78,91.664 to 20.78,45.944 on M4-Bottom Dimensions
23.32,91.664 to 66.5,89.124 on M4-Bottom Dimensions
69.04,89.124 to 88,110 on M4-Bottom Dimensions
20.78,91.664 to 2,110 on M4-Bottom Dimensions
69.04,89.124 to 90,108 on M4-Bottom Dimensions
20.78,91.664 to 69.04,89.124 on M4-Bottom Dimensions
5,5 to 85,5 on M3-Top Dimensions
5,5 to 5,105 on M3-Top Dimensions
2,0 to 2,110 on M3-Top Dimensions
0,2 to 90,2 on M3-Top Dimensions
83.241,72.252 to 79.25,75.375 on M3-Top Dimensions
60.204,78.74 to 61.6,77.8 on M3-Top Dimensions
5,5 to 0,2 on M3-Top Dimensions
5,5 to 2,0 on M3-Top Dimensions
6.7,5.257 to 9.875,6.75 on M3-Top Dimensions
14.006,48.185 to 10.975,46.1 on M3-Top Dimensions
60.204,78.74 to 83.241,72.252 on M3-Top Dimensions
40.074,78.74 to 15.579,48.979 on M3-Top Dimensions
60.204,78.74 to 58.519,53.51 on M3-Top Dimensions
40.074,78.74 to 15.579,48.979 on M3-Top Dimensions
60.204,78.74 to 83.241,72.252 on M3-Top Dimensions
60.204,78.74 to 90.024,77.825 on M3-Top Dimensions
60.204,78.74 to 61.475,110 on M3-Top Dimensions
2,110 to 2,0 on M2-Board Dimensions
0,108 to 90,108 on M2-Board Dimensions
